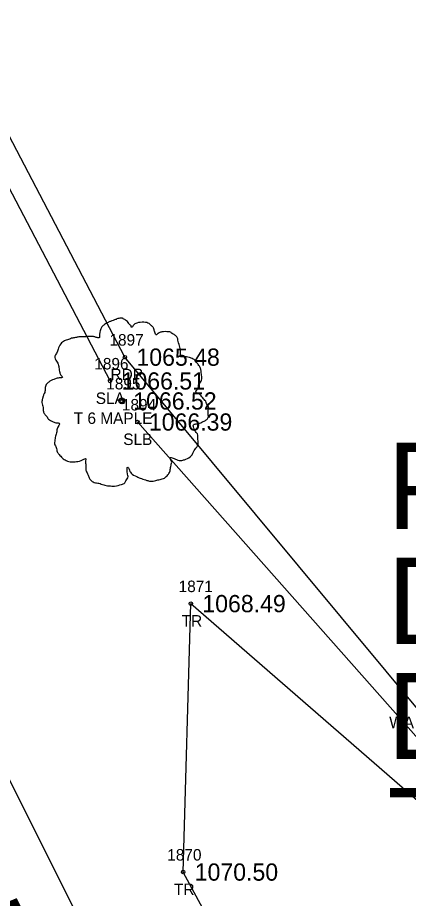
# Model space of a CAD drawing. Extents: x 1578957 to 1581675, y 1115963 to 1120391.
# Drawn here: x 1580415.9 to 1580449.8, y 1116610.9 to 1116687.4 of the extents above; entities that cross this region are included whole.
import ezdxf

# ---------------------------------------------------------------- set-up
doc = ezdxf.new("R2010")
doc.units = 0
for name, color, linetype in [('RD_EX_DR_ErosCtrl', 7, 'Continuous'), ('RD_EX_DR_ErosCtrl_txCode', 7, 'Continuous'), ('RD_EX_Misc_txCode', 7, 'Continuous'), ('RD_EX_Road', 7, 'Continuous'), ('RD_EX_TX_DR_ErosCtrl_ELEV', 7, 'Continuous'), ('RD_EX_TX_VEG_ELEV', 7, 'Continuous'), ('RD_EX_VEG', 7, 'Continuous'), ('RD_EX_VEG_txCode', 7, 'Continuous'), ('RD_HC_Data', 7, 'Continuous'), ('RD_SMD_Locator', 7, 'Continuous')]:
    doc.layers.add(name, color=color, linetype=linetype)

msp = doc.modelspace()

# ---------------------------------------------------------------- linework, layer by layer
at = {"layer": 'RD_EX_DR_ErosCtrl'}
msp.add_lwpolyline([(1580451.644, 1116626.145), (1580425.185, 1116657.937), (1580401.684, 1116702.858), (1580396.655, 1116727.542), (1580408.781, 1116735.401), (1580424.859, 1116730.997)], dxfattribs=at)
at = {"layer": 'RD_EX_Road'}
msp.add_lwpolyline([(1580570.709, 1116498.672), (1580529.362, 1116480.651), (1580519.915, 1116479.429), (1580510.641, 1116479.835), (1580504.137, 1116481.669), (1580497.171, 1116485.134), (1580490.265, 1116490.584), (1580483.828, 1116498.293), (1580485.045, 1116499.021), (1580478.372, 1116510.012), (1580451.149, 1116557.411), (1580425.988, 1116599.549), (1580403.293, 1116644.829), (1580382.317, 1116688.414), (1580373.948, 1116705.146), (1580352.793, 1116744.505), (1580332.459, 1116780.718), (1580308.505, 1116820.533), (1580282.289, 1116862.52), (1580254.512, 1116905.196), (1580227.498, 1116946.748), (1580201.695, 1116988.255)], dxfattribs=at)
at = {"layer": 'RD_EX_VEG'}
for p, q in [((1580423.894, 1116655.865), (1580403.209, 1116695.395)), ((1580455.285, 1116619.564), (1580426.269, 1116652.3))]:
    msp.add_line(p, q, dxfattribs=at)
msp.add_lwpolyline([(1580554.83, 1116529.799), (1580522.599, 1116521.054), (1580499.55, 1116521.889), (1580486.991, 1116529.007), (1580480.919, 1116539.401), (1580469.376, 1116550.646), (1580446.967, 1116582.296), (1580430.252, 1116613.188), (1580430.916, 1116636.517), (1580480.488, 1116593.462), (1580500.915, 1116561.595), (1580554.83, 1116529.799)], dxfattribs=at)
for centre, radius in [((1580424.909, 1116654.13), 0.25), ((1580424.896, 1116654.111), 0.0001)]:
    msp.add_circle(centre, radius, dxfattribs=at)
for points in [[(1580425.04, 1116661.297), (1580424.741, 1116661.322), (1580424.416, 1116661.222), (1580424.166, 1116661.122), (1580423.941, 1116661.047), (1580423.716, 1116660.947), (1580423.416, 1116660.772), (1580423.191, 1116660.573), (1580423.066, 1116660.323), (1580423.016, 1116660.098), (1580422.966, 1116659.823), (1580422.966, 1116659.648), (1580422.841, 1116659.623), (1580422.691, 1116659.648), (1580422.442, 1116659.723), (1580422.192, 1116659.723), (1580421.942, 1116659.723), (1580421.592, 1116659.698), (1580421.242, 1116659.698), (1580420.967, 1116659.648), (1580420.642, 1116659.598), (1580420.268, 1116659.473), (1580419.918, 1116659.348), (1580419.618, 1116659.098), (1580419.368, 1116658.623), (1580419.243, 1116658.274), (1580419.093, 1116658.024), (1580419.243, 1116657.574), (1580419.418, 1116657.224), (1580419.443, 1116657.024), (1580419.518, 1116656.599), (1580419.618, 1116656.374), (1580419.743, 1116656.174), (1580419.668, 1116656.15), (1580419.293, 1116656.1), (1580418.993, 1116656), (1580418.568, 1116655.775), (1580418.343, 1116655.55), (1580418.243, 1116655.225), (1580418.218, 1116654.875), (1580418.119, 1116654.675), (1580418.044, 1116654.4), (1580418.019, 1116654.325), (1580417.969, 1116654), (1580418.069, 1116653.551), (1580418.094, 1116653.201), (1580418.218, 1116652.976), (1580418.368, 1116652.801), (1580418.543, 1116652.551), (1580418.943, 1116652.326), (1580419.268, 1116652.226), (1580419.468, 1116652.201), (1580419.293, 1116651.701), (1580419.243, 1116651.352), (1580419.118, 1116650.952), (1580419.118, 1116650.877), (1580419.068, 1116650.402), (1580419.218, 1116650.077), (1580419.293, 1116649.702), (1580419.468, 1116649.477), (1580419.743, 1116649.177), (1580420.068, 1116648.953), (1580420.567, 1116648.828), (1580420.967, 1116648.853), (1580421.542, 1116649.028), (1580421.792, 1116649.103), (1580421.767, 1116648.928), (1580421.792, 1116648.553), (1580421.792, 1116648.128), (1580421.942, 1116647.803), (1580422.042, 1116647.528), (1580422.192, 1116647.278), (1580422.517, 1116647.053), (1580422.916, 1116646.978), (1580423.341, 1116646.829), (1580423.791, 1116646.754), (1580424.291, 1116646.729), (1580424.891, 1116646.878), (1580425.165, 1116647.003), (1580425.265, 1116647.178), (1580425.465, 1116647.553), (1580425.415, 1116647.778), (1580425.44, 1116648.378), (1580425.54, 1116648.203), (1580425.715, 1116647.853), (1580426.215, 1116647.553), (1580426.615, 1116647.378), (1580427.09, 1116647.228), (1580427.389, 1116647.153), (1580427.864, 1116647.228), (1580428.239, 1116647.303), (1580428.614, 1116647.428), (1580428.914, 1116647.703), (1580429.089, 1116647.978), (1580429.139, 1116648.253), (1580429.214, 1116648.628), (1580429.264, 1116648.803)], [(1580429.264, 1116648.803), (1580429.189, 1116648.978), (1580429.139, 1116649.228), (1580429.214, 1116649.202), (1580429.389, 1116649.153), (1580429.663, 1116649.028), (1580429.888, 1116648.953), (1580430.213, 1116648.978), (1580430.488, 1116649.078), (1580430.938, 1116649.353), (1580431.213, 1116649.827), (1580431.488, 1116650.227), (1580431.563, 1116650.552), (1580431.513, 1116650.777), (1580431.488, 1116651.277), (1580431.288, 1116651.526), (1580431.238, 1116651.651), (1580431.138, 1116652.051), (1580431.213, 1116652.101), (1580431.488, 1116652.151), (1580431.862, 1116652.276), (1580432.137, 1116652.401), (1580432.362, 1116652.576), (1580432.437, 1116652.801), (1580432.412, 1116653.201), (1580432.462, 1116653.601), (1580432.387, 1116653.751), (1580432.287, 1116653.9), (1580432.212, 1116654.1), (1580432.062, 1116654.25), (1580431.962, 1116654.4), (1580431.862, 1116654.5), (1580431.738, 1116654.65), (1580431.563, 1116654.775), (1580431.413, 1116654.825), (1580431.363, 1116654.975), (1580431.513, 1116655.175), (1580431.563, 1116655.275), (1580431.588, 1116655.5), (1580431.813, 1116655.85), (1580431.862, 1116656.249), (1580431.813, 1116656.674), (1580431.763, 1116656.949), (1580431.613, 1116657.224), (1580431.413, 1116657.474), (1580431.288, 1116657.649), (1580431.113, 1116657.774), (1580430.788, 1116657.899), (1580430.538, 1116657.949), (1580430.188, 1116657.949), (1580429.988, 1116657.999), (1580430.013, 1116658.049), (1580430.013, 1116658.199), (1580430.013, 1116658.474), (1580429.938, 1116658.923), (1580429.788, 1116659.423), (1580429.788, 1116659.448), (1580429.688, 1116659.698), (1580429.464, 1116659.898), (1580429.289, 1116659.998), (1580429.089, 1116660.123), (1580428.839, 1116660.148), (1580428.539, 1116660.148), (1580428.264, 1116660.098), (1580428.064, 1116659.998), (1580427.889, 1116659.873), (1580427.814, 1116660.023), (1580427.714, 1116660.323), (1580427.664, 1116660.473), (1580427.514, 1116660.647), (1580427.29, 1116660.847), (1580426.84, 1116660.972), (1580426.215, 1116660.897), (1580425.915, 1116660.698), (1580425.765, 1116660.523), (1580425.715, 1116660.647), (1580425.515, 1116660.847), (1580425.415, 1116661.022), (1580425.24, 1116661.147), (1580425.09, 1116661.247), (1580424.99, 1116661.297)]]:
    msp.add_spline(points, degree=3, dxfattribs=at)
at = {"layer": 'RD_SMD_Locator'}
for centre in [(1580425.185, 1116657.937), (1580423.894, 1116655.865), (1580424.909, 1116654.13), (1580426.269, 1116652.3), (1580430.916, 1116636.517), (1580430.252, 1116613.188)]:
    msp.add_circle(centre, 0.15, dxfattribs=at)

# ---------------------------------------------------------------- texts
at = {"layer": 'RD_EX_DR_ErosCtrl_txCode'}
for s, p in [('1897', (1580423.839, 1116658.937)), ('RDP', (1580423.933, 1116655.937))]:
    msp.add_text(s, height=1, dxfattribs=at).set_placement(p)
at = {"layer": 'RD_EX_Misc_txCode'}
msp.add_text('WA 12 BLOCK', height=1, dxfattribs=at).set_placement((1580448.16, 1116625.691))
at = {"layer": 'RD_EX_TX_DR_ErosCtrl_ELEV'}
msp.add_text('1065.48', height=1.5, dxfattribs=at).set_placement((1580426.185, 1116657.187))
at = {"layer": 'RD_EX_TX_VEG_ELEV'}
for s, p in [('1066.51', (1580424.894, 1116655.115)), ('1066.52', (1580425.909, 1116653.38)), ('1066.39', (1580427.269, 1116651.55)), ('1068.49', (1580431.916, 1116635.767)), ('1070.50', (1580431.252, 1116612.438))]:
    msp.add_text(s, height=1.5, dxfattribs=at).set_placement(p)
at = {"layer": 'RD_EX_VEG_txCode'}
for s, p in [('1896', (1580422.523, 1116656.865)), ('1895', (1580423.562, 1116655.13)), ('SLA', (1580422.649, 1116653.865)), ('1894', (1580424.923, 1116653.3)), ('T 6 MAPLE', (1580420.739, 1116652.13)), ('SLB', (1580425.041, 1116650.3)), ('1871', (1580429.853, 1116637.517)), ('TR', (1580430.12, 1116634.517)), ('1870', (1580428.866, 1116614.188)), ('TR', (1580429.456, 1116611.188))]:
    msp.add_text(s, height=1, dxfattribs=at).set_placement(p)
at = {"layer": 'RD_HC_Data'}
for s, p in [('P.I. = 10+92.71', (1580448, 1116643)), ('D', (1580448, 1116633)), ('D = 14%%d 19\' 28"', (1580448, 1116623)), ("T = 15.50'", (1580448, 1116613))]:
    msp.add_text(s, height=7.5, dxfattribs=at).set_placement(p)
msp.add_text('N 25%%d 54\' 34" W', height=6, rotation=295.90948, dxfattribs=at).set_placement((1580400.311, 1116629.039))

doc.saveas('drawing.dxf')
